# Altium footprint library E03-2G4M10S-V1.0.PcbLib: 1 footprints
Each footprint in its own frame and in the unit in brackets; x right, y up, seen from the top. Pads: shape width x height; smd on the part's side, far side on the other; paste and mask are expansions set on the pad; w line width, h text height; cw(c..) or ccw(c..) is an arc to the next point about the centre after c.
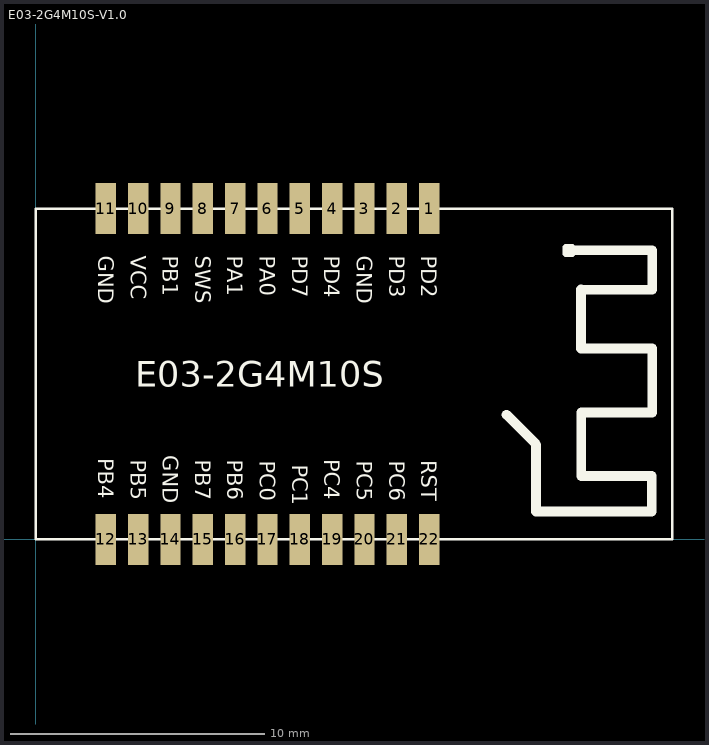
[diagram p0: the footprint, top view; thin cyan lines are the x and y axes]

## E03-2G4M10S-V1.0 [mm]
pads (22):
  rect 0.8x2 smd: 1(15.45,13) 2(14.18,13) 3(12.91,13) 4(11.64,13) 5(10.37,13) 6(9.1,13) 7(7.83,13) 8(6.56,13) 9(5.29,13) 10(4.02,13) 11(2.75,13) 12(2.75,0) 13(4.02,0) 14(5.29,0) 15(6.56,0) 16(7.83,0) 17(9.1,0) 18(10.37,0) 19(11.64,0) 20(12.91,0) 21(14.18,0) 22(15.45,0)
Top Overlay:
  lines w0.1: 0,0 25,0 25,13 0,13 0,0
  lines w0.254: 21.071,11.232 20.817,11.232 20.817,11.486 21.071,11.486
  lines w0.381: 18.49,4.905 19.646,3.749 ; 19.649,3.714 19.649,1.098 24.196,1.098 24.196,2.495 21.427,2.495 21.427,4.984 24.221,4.985 24.221,7.499 21.427,7.499 ; 20.944,11.359 24.221,11.359 ; 21.415,7.505 21.415,9.816 ; 21.427,9.811 24.221,9.811 ; 24.221,9.81 24.221,11.36
  text "E03-2G4M10S" at 3.9,6 h1
  text "PB7" at 6.26,3.137 h0.6
  text "PC0" at 8.8,3.086 h0.6
  text "PC1" at 10.07,2.943 h0.6
  text "PB6" at 7.53,3.137 h0.6
  text "PC5" at 12.61,3.086 h0.6
  text "PB4" at 2.45,3.194 h0.6
  text "GND" at 4.99,3.3 h0.6
  text "RST" at 15.15,3.114 h0.6
  text "PC6" at 13.88,3.086 h0.6
  text "PC4" at 11.34,3.143 h0.6
  text "PB5" at 3.72,3.137 h0.6
  text "PA1" at 7.53,11.15 h0.6
  text "PD7" at 10.07,11.15 h0.6
  text "PD4" at 11.34,11.15 h0.6
  text "GND" at 2.45,11.15 h0.6
  text "PD3" at 13.88,11.15 h0.6
  text "SWS" at 6.26,11.15 h0.6
  text "PD2" at 15.15,11.15 h0.6
  text "PB1" at 4.99,11.15 h0.6
  text "PA0" at 8.8,11.15 h0.6
  text "GND" at 12.61,11.15 h0.6
  text "VCC" at 3.72,11.15 h0.6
